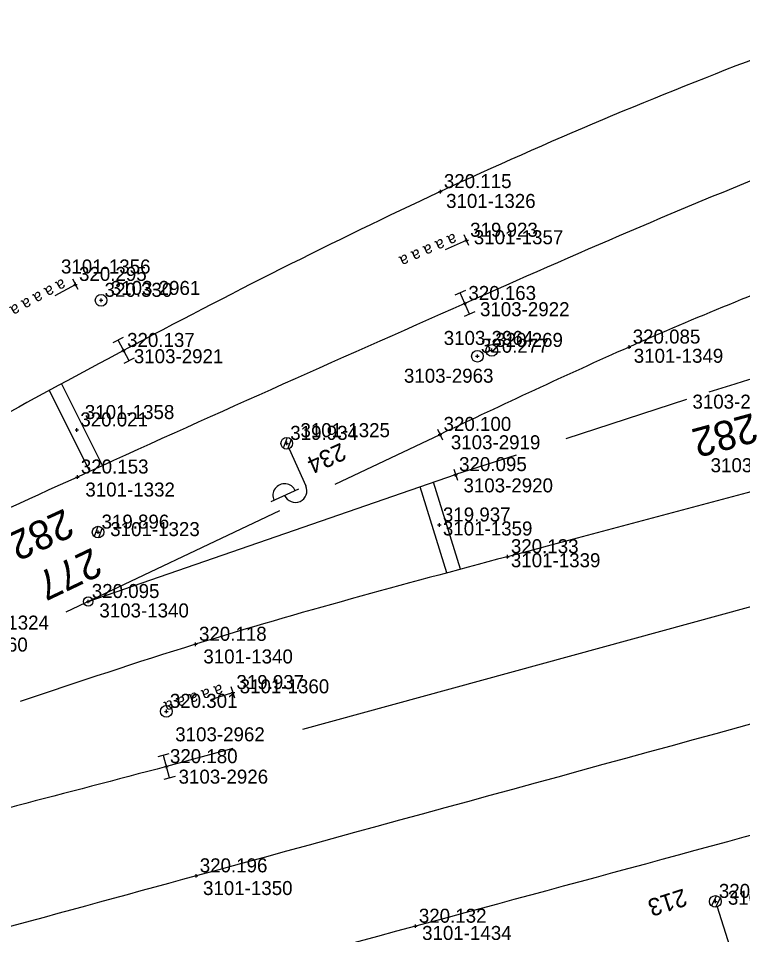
# Model space of a CAD drawing. Extents: x -821875 to -821475, y -1070280 to -1069975.
# Drawn here: x -821748.89 to -821717.84, y -1070211.76 to -1070172.51 of the extents above; entities that cross this region are included whole.
import ezdxf

# ---------------------------------------------------------------- set-up
doc = ezdxf.new("R2010")
doc.units = 0
for name, color, linetype in [('Vrstva 1', 7, 'Continuous'), ('Vrstva 11', 7, 'Continuous'), ('Vrstva 2', 7, 'Continuous'), ('Vrstva 25', 7, 'Continuous'), ('Vrstva 28', 7, 'Continuous'), ('Vrstva 3', 7, 'Continuous'), ('Vrstva 6', 7, 'Continuous'), ('Vrstva 60', 7, 'Continuous'), ('Vrstva 61', 7, 'Continuous'), ('Vrstva 7', 7, 'Continuous')]:
    doc.layers.add(name, color=color, linetype=linetype)

# ---------------------------------------------------------------- blocks, each defined once
blk = doc.blocks.new('BOD')
at = {"layer": 'Vrstva 3'}
for p, q in [((-0.15, 0), (0.15, 0)), ((0, -0.15), (0, 0.15))]:
    blk.add_line(p, q, dxfattribs=at)

msp = doc.modelspace()

# ---------------------------------------------------------------- linework, layer by layer
at = {"layer": 'Vrstva 1'}
for p, q in [((-821720.251, -1070188.838), (-821725.422, -1070190.522)), ((-821727.557, -1070191.217), (-821730.147, -1070192.052))]:
    msp.add_line(p, q, dxfattribs=at)
for points in [[(-821711.133, -1070195.974), (-821736.713, -1070202.967)], [(-821739.69, -1070203.781), (-821742.542, -1070204.561)]]:
    msp.add_lwpolyline(points, dxfattribs=at)
for points in [[(-821679.285, -1070162.663), (-821695.528, -1070167.095), (-821716.799, -1070174.043), (-821730.799, -1070179.932), (-821744.379, -1070186.736), (-821755.356, -1070192.851), (-821764.427, -1070198.469)], [(-821677.113, -1070166.912), (-821699.427, -1070173.07), (-821715.575, -1070178.704), (-821729.749, -1070184.723), (-821746.361, -1070192.156), (-821759.601, -1070198.262)], [(-821682.977, -1070173.434), (-821704.603, -1070179.855), (-821714.119, -1070183.088), (-821722.706, -1070186.589), (-821730.813, -1070190.332)], [(-821700.898, -1070183.216), (-821713.391, -1070186.695), (-821719.286, -1070188.528)], [(-821714.233, -1070191.924), (-821727.927, -1070195.569), (-821741.295, -1070199.32), (-821748.807, -1070201.766)], [(-821710.276, -1070200.761), (-821741.264, -1070209.238), (-821760.235, -1070214.402), (-821776.338, -1070219.041), (-821794.464, -1070225.772), (-821811.866, -1070233.595), (-821823.5, -1070239.204)], [(-821742.542, -1070204.561), (-821755.391, -1070207.946), (-821768.915, -1070211.875), (-821773.964, -1070213.578)], [(-821709.336, -1070205.287), (-821731.872, -1070211.395), (-821757.763, -1070218.461), (-821767.367, -1070221.229)]]:
    msp.add_spline(points, degree=3, dxfattribs=at)
at = {"layer": 'Vrstva 11'}
for p, q in [((-821745.476, -1070194.268), (-821745.637, -1070194.702)), ((-821745.302, -1070194.337), (-821745.461, -1070194.764))]:
    msp.add_line(p, q, dxfattribs=at)
msp.add_circle((-821745.473, -1070194.516), 0.25, dxfattribs=at)
at = {"layer": 'Vrstva 2'}
for p, q in [((-821730.92, -1070190.106), (-821730.706, -1070190.558)), ((-821730.228, -1070191.816), (-821730.066, -1070192.288))]:
    msp.add_line(p, q, dxfattribs=at)
for points in [[(-821735.304, -1070192.463), (-821730.813, -1070190.332)], [(-821745.892, -1070197.488), (-821730.147, -1070192.052)], [(-821746.835, -1070197.936), (-821737.688, -1070193.595)]]:
    msp.add_lwpolyline(points, dxfattribs=at)
msp.add_circle((-821745.892, -1070197.488), 0.2, dxfattribs=at)
at = {"layer": 'Vrstva 25'}
for p, q in [((-821737.365, -1070190.466), (-821737.534, -1070190.913)), ((-821737.196, -1070190.55), (-821737.352, -1070190.96)), ((-821737.282, -1070190.942), (-821736.564, -1070192.538)), ((-821736.883, -1070192.681), (-821738.068, -1070193.215)), ((-821718.965, -1070210.087), (-821719.184, -1070210.513)), ((-821718.807, -1070210.19), (-821719.008, -1070210.581)), ((-821718.935, -1070210.57), (-821718.402, -1070212.237))]:
    msp.add_line(p, q, dxfattribs=at)
for centre in [(-821737.384, -1070190.714), (-821737.384, -1070190.714), (-821719.012, -1070210.332), (-821719.012, -1070210.332)]:
    msp.add_circle(centre, 0.25, dxfattribs=at)
for centre, start, end in [((-821737.478, -1070192.943), 23.5156, 204.9208), ((-821737.02, -1070192.743), 204.2182, 24.2182)]:
    msp.add_arc(centre, 0.5, start, end, dxfattribs=at)
at = {"layer": 'Vrstva 28'}
for p, q in [((-821745.368, -1070184.588), (-821745.318, -1070184.588)), ((-821729.237, -1070186.983), (-821729.187, -1070186.983)), ((-821728.622, -1070186.733), (-821728.572, -1070186.733)), ((-821742.571, -1070202.192), (-821742.521, -1070202.192))]:
    msp.add_line(p, q, dxfattribs=at)
for centre in [(-821745.343, -1070184.588), (-821728.597, -1070186.733), (-821729.212, -1070186.983), (-821742.546, -1070202.192)]:
    msp.add_circle(centre, 0.25, dxfattribs=at)
at = {"layer": 'Vrstva 3'}
for p, q in [((-821729.724, -1070184.165), (-821730.18, -1070184.368)), ((-821729.546, -1070185.18), (-821729.952, -1070184.266)), ((-821729.318, -1070185.078), (-821729.774, -1070185.281)), ((-821744.394, -1070186.177), (-821744.835, -1070186.413)), ((-821744.144, -1070187.177), (-821744.614, -1070186.295)), ((-821743.923, -1070187.059), (-821744.364, -1070187.295)), ((-821742.433, -1070204.013), (-821742.915, -1070204.145)), ((-821742.41, -1070205.043), (-821742.674, -1070204.079)), ((-821742.169, -1070204.977), (-821742.651, -1070205.109))]:
    msp.add_line(p, q, dxfattribs=at)
at = {"layer": 'Vrstva 6'}
for p, q in [((-821729.575, -1070182.244), (-821729.773, -1070181.786)), ((-821730.583, -1070182.408), (-821729.674, -1070182.015)), ((-821747.31, -1070184.377), (-821746.439, -1070183.906)), ((-821746.32, -1070184.126), (-821746.558, -1070183.686)), ((-821739.616, -1070201.625), (-821739.766, -1070201.149)), ((-821740.636, -1070201.683), (-821739.691, -1070201.387))]:
    msp.add_line(p, q, dxfattribs=at)
at = {"layer": 'Vrstva 7'}
for p, q in [((-821745.285, -1070191.661), (-821747.042, -1070188.154)), ((-821745.83, -1070191.911), (-821747.571, -1070188.437)), ((-821730.517, -1070196.253), (-821731.666, -1070192.577)), ((-821729.936, -1070196.1), (-821731.099, -1070192.381))]:
    msp.add_line(p, q, dxfattribs=at)

# ---------------------------------------------------------------- block references
at = {"layer": 'Vrstva 60', "xscale": 0.5, "yscale": 0.5}
for p in [(-821730.799, -1070179.932), (-821729.674, -1070182.015), (-821746.439, -1070183.906), (-821745.343, -1070184.588), (-821729.749, -1070184.723), (-821744.379, -1070186.736), (-821728.597, -1070186.733), (-821722.706, -1070186.589), (-821729.212, -1070186.983), (-821746.383, -1070190.139), (-821730.813, -1070190.332), (-821737.384, -1070190.714), (-821746.361, -1070192.156), (-821730.147, -1070192.052), (-821730.841, -1070194.21), (-821745.473, -1070194.516), (-821727.927, -1070195.569), (-821745.892, -1070197.488), (-821741.295, -1070199.32), (-821739.691, -1070201.387), (-821742.546, -1070202.192), (-821742.542, -1070204.561), (-821741.264, -1070209.238), (-821719.012, -1070210.332), (-821731.872, -1070211.395)]:
    msp.add_blockref('BOD', p, dxfattribs=at)

# ---------------------------------------------------------------- texts
at = {"layer": 'Vrstva 11'}
for s, rotation, p in [('282', 195.1705, (-821717.41, -1070189.403)), ('282A', 204.6049, (-821746.907, -1070193.486))]:
    msp.add_text(s, height=1.25, rotation=rotation, dxfattribs=at).set_placement(p)
at = {"layer": 'Vrstva 2'}
msp.add_text('277', height=1.25, rotation=205.389, dxfattribs=at).set_placement((-821745.715, -1070195.16))
at = {"layer": 'Vrstva 25'}
for s, rotation, p in [('234', 204.2181, (-821735.062, -1070190.674)), ('213', 197.8055, (-821720.377, -1070209.771))]:
    msp.add_text(s, height=0.75, rotation=rotation, dxfattribs=at).set_placement(p)
at = {"layer": 'Vrstva 6'}
for rotation, p in [(203.3931, (-821729.872, -1070181.555)), (208.4248, (-821746.676, -1070183.466)), (197.3921, (-821739.84, -1070200.91))]:
    msp.add_text('  a a a a a', height=0.5, rotation=rotation, dxfattribs=at).set_placement(p)
at = {"layer": 'Vrstva 60'}
for s, p in [('3101-1326', (-821730.555, -1070180.631)), ('3101-1357', (-821729.368, -1070182.186)), ('3101-1356', (-821747.062, -1070183.439)), ('3103-2961', (-821744.927, -1070184.357)), ('3103-2922', (-821729.101, -1070185.267)), ('3103-2964', (-821730.657, -1070186.499)), ('3103-2921', (-821743.939, -1070187.283)), ('3101-1349', (-821722.511, -1070187.263)), ('3103-2963', (-821732.361, -1070188.117)), ('3103-2965', (-821719.995, -1070189.228)), ('3101-1358', (-821746.04, -1070189.673)), ('3101-1325', (-821736.798, -1070190.449)), ('3103-2919', (-821730.351, -1070190.968)), ('3103-2925', (-821719.216, -1070191.95)), ('3101-1332', (-821746.017, -1070192.992)), ('3103-2920', (-821729.81, -1070192.813)), ('3101-1323', (-821744.951, -1070194.687)), ('3101-1359', (-821730.691, -1070194.66)), ('3101-1339', (-821727.777, -1070196.019)), ('3103-1340', (-821745.417, -1070198.17)), ('3101-1324', (-821751.415, -1070198.691)), ('3103-2960', (-821752.323, -1070199.632)), ('3101-1340', (-821740.959, -1070200.141)), ('3101-1360', (-821739.402, -1070201.42)), ('3103-2962', (-821742.164, -1070203.476)), ('3103-2926', (-821742.021, -1070205.289)), ('3101-1350', (-821740.974, -1070210.059)), ('3101-1361', (-821718.475, -1070210.473)), ('3101-1434', (-821731.583, -1070211.984))]:
    msp.add_text(s, height=0.6, dxfattribs=at).set_placement(p)
at = {"layer": 'Vrstva 61'}
for s, p in [('320.115', (-821730.649, -1070179.782)), ('319.923', (-821729.524, -1070181.865)), ('320.295', (-821746.289, -1070183.756)), ('320.330', (-821745.193, -1070184.438)), ('320.163', (-821729.599, -1070184.573)), ('320.085', (-821722.556, -1070186.439)), ('320.137', (-821744.229, -1070186.586)), ('320.277', (-821729.062, -1070186.833)), ('320.269', (-821728.447, -1070186.583)), ('320.021', (-821746.233, -1070189.989)), ('320.100', (-821730.663, -1070190.182)), ('319.934', (-821737.234, -1070190.564)), ('320.153', (-821746.211, -1070192.006)), ('320.095', (-821729.997, -1070191.902)), ('319.896', (-821745.323, -1070194.366)), ('319.937', (-821730.691, -1070194.06)), ('320.133', (-821727.777, -1070195.419)), ('320.095', (-821745.742, -1070197.338)), ('320.118', (-821741.145, -1070199.17)), ('319.937', (-821739.541, -1070201.237)), ('320.301', (-821742.396, -1070202.042)), ('320.180', (-821742.392, -1070204.411)), ('320.196', (-821741.114, -1070209.088)), ('320.238', (-821718.862, -1070210.182)), ('320.132', (-821731.722, -1070211.245))]:
    msp.add_text(s, height=0.6, dxfattribs=at).set_placement(p)

doc.saveas('drawing.dxf')
